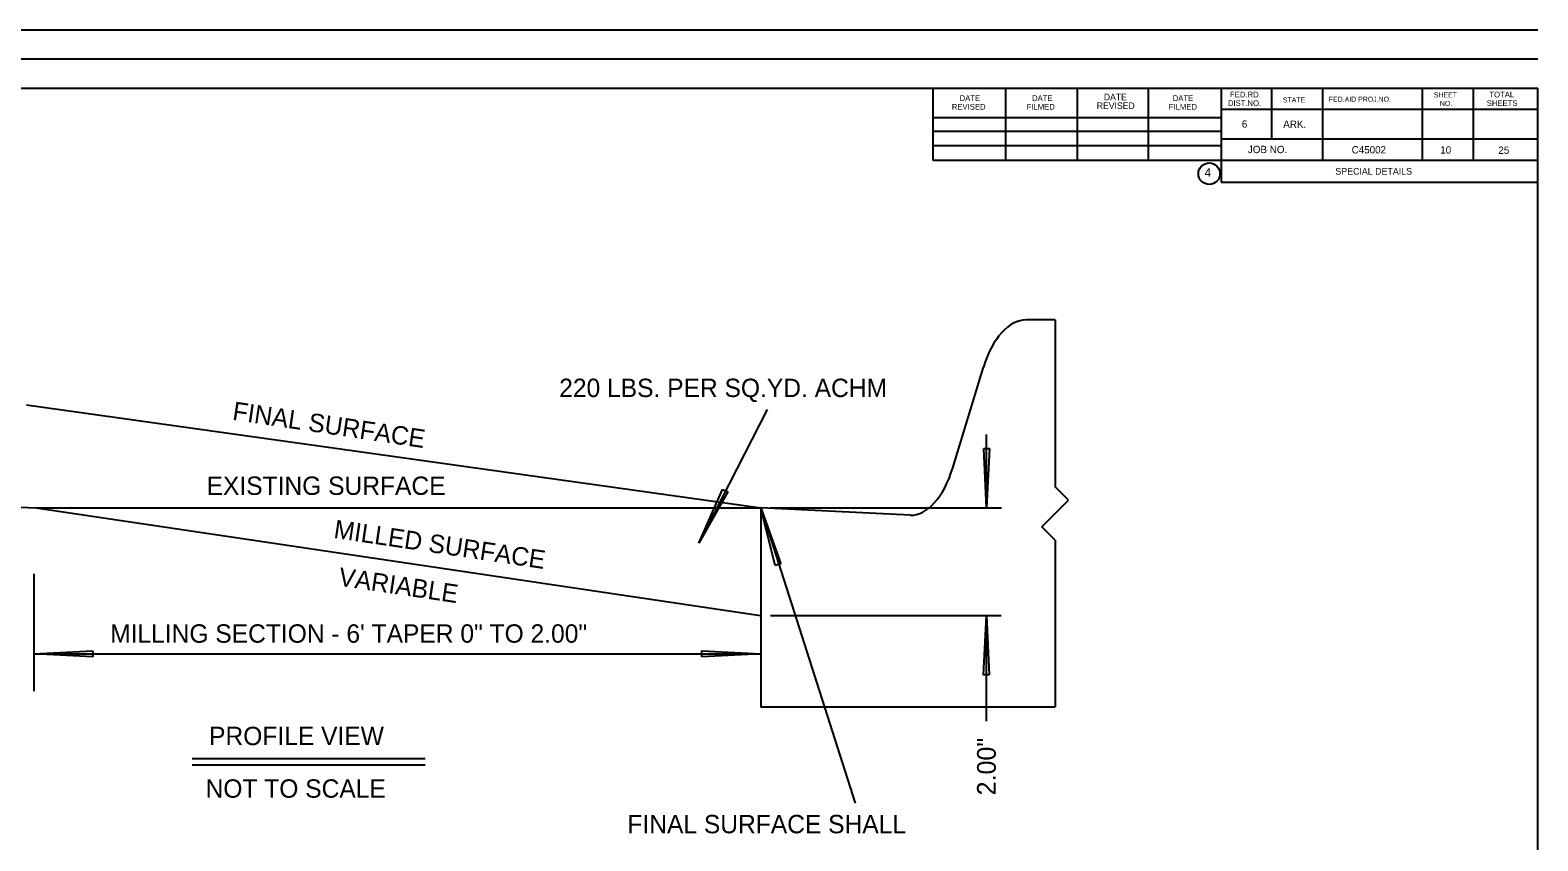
# Model space of a CAD drawing. Extents: x 1944905 to 1956777, y 763871 to 764977.
# Drawn here: x 1955751 to 1956777, y 764425 to 764977 of the extents above; entities that cross this region are included whole.
import ezdxf

# ---------------------------------------------------------------- set-up
doc = ezdxf.new("R2010")
doc.units = 0
for name, color, linetype in [('Default', 7, 'Continuous'), ('R_Border', 7, 'Continuous'), ('R_Dimension', 7, 'Continuous')]:
    doc.layers.add(name, color=color, linetype=linetype)

# ---------------------------------------------------------------- blocks, each defined once
blk = doc.blocks.new('AHD')
at = {"layer": 'R_Dimension'}
for p, q in [((0, 0), (0.796, 1.837)), ((0.975, 1.749), (0, 0)), ((0.796, 1.837), (0.975, 1.749)), ((0.978, 1.754), (0.975, 1.749))]:
    blk.add_line(p, q, dxfattribs=at)

msp = doc.modelspace()

# ---------------------------------------------------------------- linework, layer by layer
at = {"layer": 'Default'}
for p, q in [((1956776.6, 764976.7), (1955157.9, 764976.7)), ((1956776.6, 764957), (1955157.9, 764957)), ((1955195.7, 764937.3), (1956776.6, 764937.3)), ((1956365.3, 764887.9), (1956365.3, 764937.3)), ((1956414.6, 764887.9), (1956414.6, 764936.3)), ((1956463.5, 764887.9), (1956463.5, 764936.3)), ((1956511.8, 764887.9), (1956511.8, 764936.3)), ((1956561.2, 764937.3), (1956561.2, 764873.3)), ((1956595.4, 764937.3), (1956595.4, 764902.6)), ((1956630, 764937.3), (1956630, 764887.9)), ((1956697.9, 764937.3), (1956697.9, 764887.9)), ((1956732.6, 764937.3), (1956732.6, 764887.9)), ((1956776.6, 763910.1), (1956776.6, 764937.3)), ((1956776.6, 764922.6), (1956561.2, 764922.6)), ((1956365.3, 764917.3), (1956561.2, 764917.3)), ((1956365.3, 764908), (1956561.2, 764908)), ((1956776.6, 764902.6), (1956561.2, 764902.6)), ((1956365.3, 764898.2), (1956561.2, 764898.2)), ((1956776.6, 764887.9), (1956365.3, 764887.9)), ((1956561.2, 764873.3), (1956776.6, 764873.3))]:
    msp.add_line(p, q, dxfattribs=at)
msp.add_circle((1956553, 764879), 7.33, dxfattribs=at)
at = {"layer": 'R_Dimension'}
for p, q in [((1956448.3, 764779.6), (1956428.5, 764779.6)), ((1956448.3, 764779.6), (1956448.3, 764666)), ((1956378.5, 764678.8), (1956399.5, 764747.3)), ((1955748.3, 764721.7), (1956247.9, 764651.5)), ((1956252.2, 764718.6), (1956205.8, 764627.5)), ((1956401.6, 764651.5), (1956401.6, 764701.6)), ((1956457.3, 764656.9), (1956448.3, 764666)), ((1955551.5, 764660.6), (1955754.9, 764651.5)), ((1956439.2, 764638.7), (1956457.3, 764656.9)), ((1955754.9, 764651.5), (1956247.7, 764578.4)), ((1955754.9, 764651.5), (1956247.9, 764651.5)), ((1956349.5, 764646.5), (1956247.9, 764651.5)), ((1956247.9, 764651.5), (1956312.1, 764450.5)), ((1956254.6, 764651.5), (1956411.6, 764651.5)), ((1956448.3, 764629.6), (1956439.2, 764638.7)), ((1956448.3, 764629.6), (1956448.3, 764516.1)), ((1955753.4, 764606.6), (1955753.4, 764526.9)), ((1956254.6, 764578.4), (1956411.4, 764578.4)), ((1956401.4, 764506.3), (1956401.4, 764578.4)), ((1955753.4, 764552.3), (1956247.9, 764552.3)), ((1955861.1, 764481), (1956019.6, 764481)), ((1955861.1, 764476.7), (1956019.6, 764476.7))]:
    msp.add_line(p, q, dxfattribs=at)
msp.add_lwpolyline([(1956247.9, 764651.5), (1956247.9, 764516.1), (1956448.3, 764516.1)], dxfattribs=at)
for centre, start_param, end_param in [((1956428.5, 764713), 3.141593, 4.171289), ((1956349.5, 764713), 0, 1.029697)]:
    msp.add_ellipse(centre, major_axis=(0, -66.5), ratio=0.509275, start_param=start_param, end_param=end_param, dxfattribs=at)

# ---------------------------------------------------------------- block references
at = {"layer": 'R_Border'}
for p, xscale, yscale, rotation in [((1956401.6, 764651.5), 19.95379363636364, 20.323922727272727, 25.86954417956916), ((1956247.9, 764651.5), 20.148073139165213, 20.127982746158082, -136.81862736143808), ((1956401.4, 764578.4), 19.953793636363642, 20.323922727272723, -154.13045581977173), ((1955753.4, 764552.3), 20.32392272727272, 19.95379363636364, -63.294229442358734), ((1956247.9, 764552.3), 20.32392272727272, 19.95379363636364, 116.78651893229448)]:
    msp.add_blockref('AHD', p, dxfattribs=dict(at, xscale=xscale, yscale=yscale, rotation=rotation))
at = {"layer": 'R_Border', "xscale": 20.32394048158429, "yscale": 19.95381106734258}
msp.add_blockref('AHD', (1956205.8, 764627.5), dxfattribs=at)

# ---------------------------------------------------------------- texts
at = {"layer": 'Default'}
for s, height, p in [('DATE', 3.91, (1956383.2, 764928.5)), ('DATE', 3.91, (1956432.5, 764928.5)), ('DATE', 4.4, (1956481.3, 764929)), ('DATE', 3.91, (1956528.2, 764928.5)), ('FED.RD.', 3.91, (1956567.2, 764930.9)), ('STATE', 3.42, (1956603.1, 764927.5)), ('FED.AID PROJ.NO.', 3.42, (1956634.4, 764928)), ('SHEET', 3.42, (1956705.8, 764930.9)), ('TOTAL', 3.91, (1956743.6, 764930.9)), ('REVISED', 3.91, (1956377.9, 764922.6)), ('FILMED', 3.91, (1956428.8, 764922.6)), ('REVISED', 4.4, (1956476.5, 764923.1)), ('FILMED', 3.91, (1956525.5, 764922.6)), ('DIST.NO.', 3.91, (1956565.7, 764925.1)), ('NO.', 3.42, (1956709.9, 764925.1)), ('SHEETS', 3.91, (1956741.8, 764925.1)), ('6', 5, (1956575.2, 764910.3)), ('ARK.', 5, (1956603.4, 764910.2)), ('JOB NO.', 5, (1956579.3, 764893)), ('C45002', 5, (1956649.9, 764892.8)), ('10', 5, (1956710.2, 764892.7)), ('25', 5, (1956749.7, 764892.5)), ('4', 5.86, (1956549.9, 764876.9)), ('SPECIAL DETAILS', 4.5, (1956638.8, 764878.4))]:
    msp.add_text(s, height=height, dxfattribs=at).set_placement(p)
at = {"layer": 'R_Dimension'}
for s, p in [('220 LBS. PER SQ.YD. ACHM', (1956110.8, 764727)), ('EXISTING SURFACE', (1955870.9, 764660.4)), ('MILLING SECTION - 6\' TAPER 0" TO 2.00"', (1955805.3, 764559.8)), ('PROFILE VIEW', (1955872.6, 764490.1)), ('NOT TO SCALE', (1955870.2, 764454.3)), ('FINAL SURFACE SHALL', (1956157.2, 764430.1))]:
    msp.add_text(s, height=12.504, dxfattribs=at).set_placement(p)
for s, height, rotation, p in [('FINAL SURFACE', 12.509, 351.5639, (1955888, 764711.6)), ('MILLED SURFACE', 12.51, 351.5639, (1955956.9, 764631.2)), ('VARIABLE', 12.51, 351.5639, (1955960.1, 764598.7)), ('2.00"', 12.74, 90, (1956407.8, 764455.9))]:
    msp.add_text(s, height=height, rotation=rotation, dxfattribs=at).set_placement(p)

doc.saveas('drawing.dxf')
